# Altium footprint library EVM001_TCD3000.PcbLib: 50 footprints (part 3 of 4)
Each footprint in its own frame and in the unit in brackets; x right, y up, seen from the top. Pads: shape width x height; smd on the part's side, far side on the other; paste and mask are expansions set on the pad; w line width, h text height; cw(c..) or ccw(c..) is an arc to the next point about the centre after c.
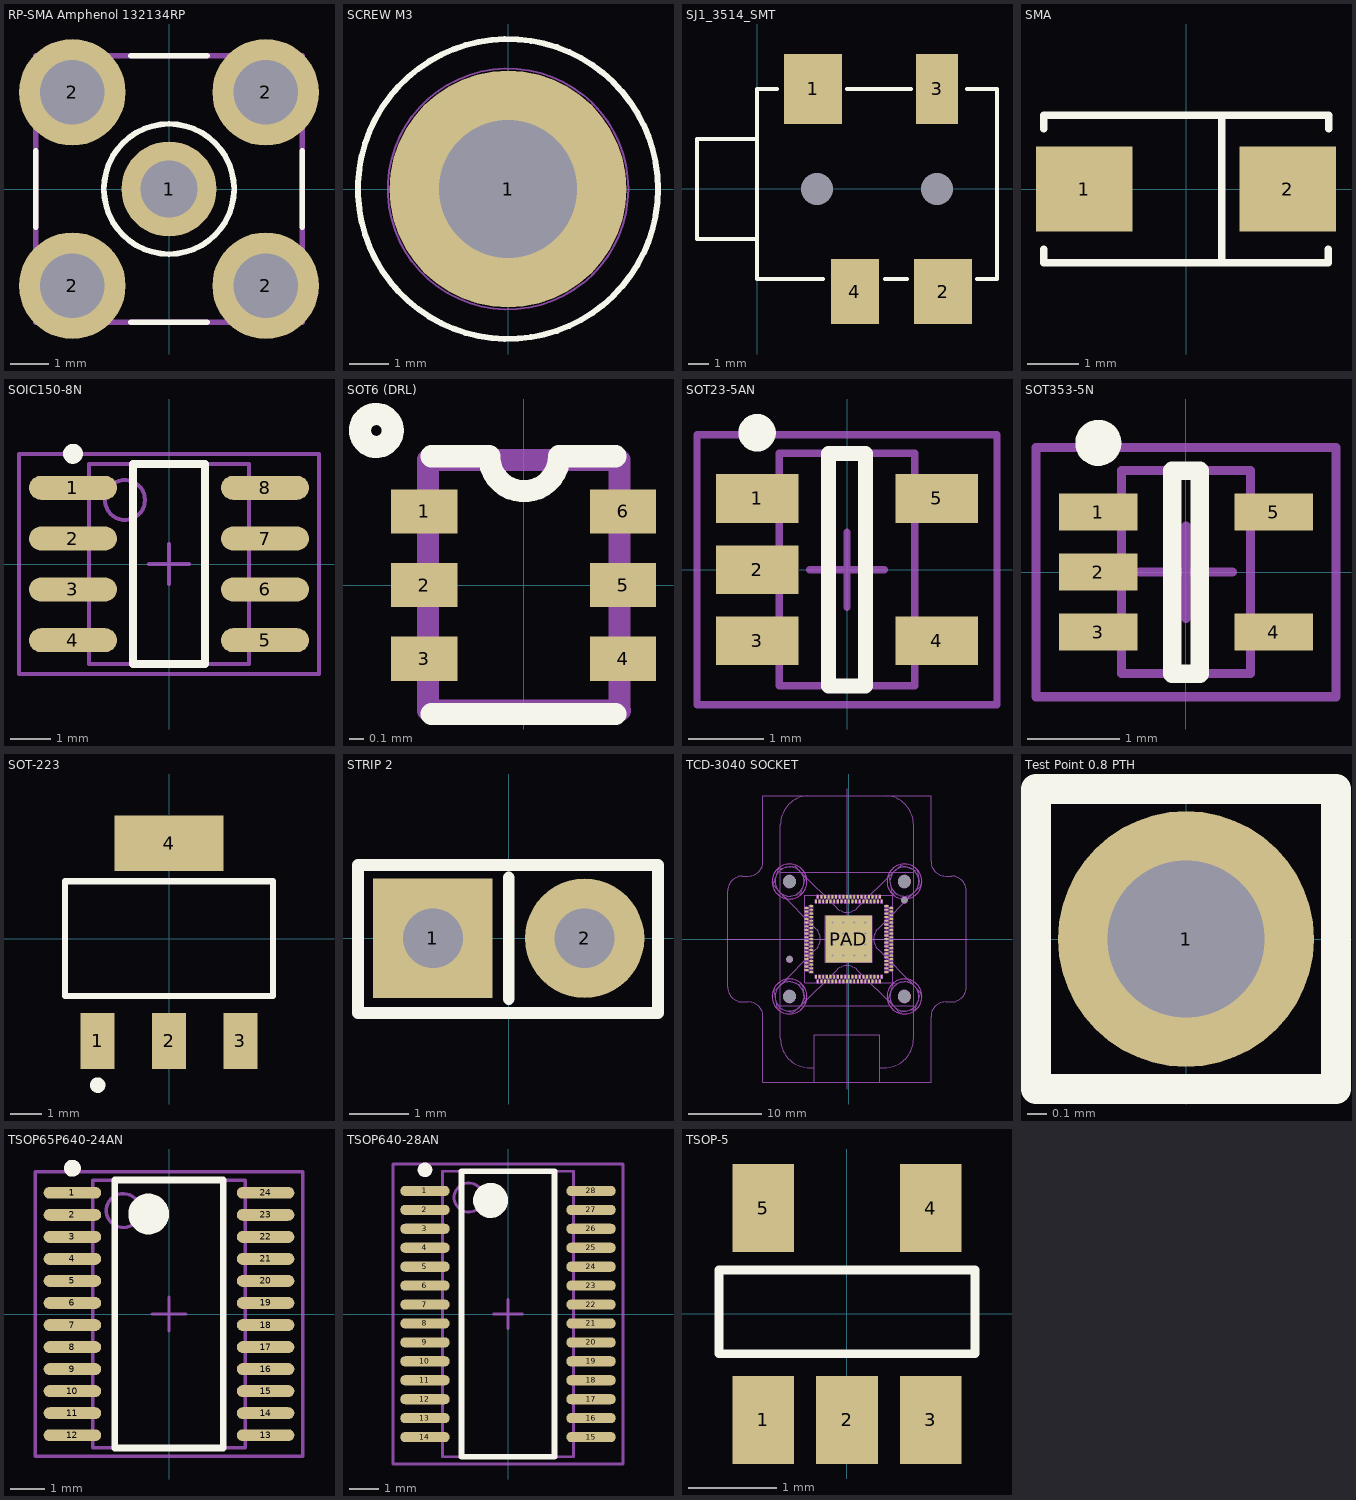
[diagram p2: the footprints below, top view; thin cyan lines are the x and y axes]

## RP-SMA Amphenol 132134RP [mm]
pads (5):
  round 2.5 hole 1.5: 1(0,0)
  round 2.8 hole 1.7: 2(-2.54,-2.54) 2(-2.54,2.54) 2(2.54,-2.54) 2(2.54,2.54)
Top Overlay:
  circle w0.15: c0,0 r1.71
  lines w0.15: -3.5,-1 -3.5,1 ; -1,-3.5 1,-3.5 ; -1,3.5 1,3.5 ; 3.5,-1 3.5,1
Mechanical 10:
  lines w0.156: -3.5,-3.5 -3.5,3.5 3.5,3.5 3.5,-3.5 -3.5,-3.5
3D body: height 9.6, standoff -3.87, extent -3.175,-3.175 3.175,3.175

## SCREW M3 [mm] "Vite 3mm"
pads (1):
  round 6 hole 3.5: 1(0,0)
Top Overlay:
  circle w0.15: c0,0 r3.8
Mechanical 10:
  circle w0.051: c0,0 r3.048
3D body: height 4, standoff 0, extent -3.057,-3.057 3.057,3.057

## SJ1_3514_SMT [mm]
pads (6):
  round 0 hole 1.6: 0(3,0) 0(9,0)
  rect 2.9x3.5 smd: 1(2.8,5)
  rect 2.9x3.25 smd: 2(9.3,-5.125)
  rect 2.1x3.5 smd: 3(9,5)
  rect 2.4x3.25 smd: 4(4.9,-5.125)
Top Overlay:
  lines w0.203: 0,-2.5 -3,-2.5 -3,2.5 0,2.5 ; 1,5 0,5 0,-4.5 3.3,-4.5 ; 4.5,5 7.7,5 ; 6.4,-4.5 7.5,-4.5 ; 10.5,5 12,5 12,-4.5 11,-4.5
3D body: height 5, standoff -2, extent -2.678,-4.912 11.822,5.588

## SMA [mm] "SMA Diodes Case"
pads (2):
  rect 1.9x1.68 smd: 1(-2,0) 2(2,0)
Top Overlay:
  lines w0.15: -2.8,-1.19 -2.8,-1.45 2.8,-1.45 2.8,-1.19 ; -2.8,1.19 -2.8,1.45 2.8,1.45 ; 0.7,-1.45 0.7,1.45 ; 2.81,1.19 2.81,1.45
3D body: height 2.4, standoff 0, extent -2.6,-1.3 2.6,1.3

## SOIC150-8N [mm]
pads (8):
  oval 2.2x0.6 smd: 1(-2.4,1.905) 2(-2.4,0.635) 3(-2.4,-0.635) 4(-2.4,-1.905) 5(2.4,-1.905) 6(2.4,-0.635) 7(2.4,0.635) 8(2.4,1.905)
Top Overlay:
  circle w0.25: c-2.4,2.755 r0.125
  lines w0.2: -0.9,-2.5 -0.9,2.5 0.9,2.5 0.9,-2.5 -0.9,-2.5
Mechanical 13:
  circle w0.1: c-1.1,1.6 r0.5
  lines w0.1: -2,-2.5 -2,2.5 2,2.5 2,-2.5 -2,-2.5
Mechanical 15:
  lines w0.1: -0.5,0 0.5,0 ; 0,-0.5 0,0.5 ; -3.75,-2.75 -3.75,2.75 3.75,2.75 3.75,-2.75 -3.75,-2.75
3D body: height 1.75, standoff 0, extent -2.917,-2.388 2.883,2.412

## SOT6 (DRL) [mm]
pads (6):
  rect 0.45x0.3 smd: 1(-0.675,0.5) 2(-0.675,0) 3(-0.675,-0.5) 4(0.675,-0.5) 5(0.675,0) 6(0.675,0.5)
Top Overlay:
  circle w0.15: c-1,1.05 r0.112
  lines w0.15: -0.625,-0.875 0.623,-0.875 ; -0.625,0.875 -0.235,0.875 ; -0.234,0.875 ccw(c0.004,0.875) 0.241,0.875 0.623,0.875
Mechanical 10:
  lines w0.15: -0.65,-0.85 -0.65,0.85 0.65,0.85 0.65,-0.85 ; -0.646,-0.85 0.654,-0.85
3D body: height 0.6, standoff 0, extent -0.65,-0.85 0.654,0.85

## SOT23-5AN [mm] "SOT23, 5-Leads, Body 2.9x1.6mm, Pitch 0.95mm, Lead Span 2.8mm, IPC Medium Density"
height 1.45
pads (5):
  rect 1.1x0.65 smd: 1(-1.2,0.95) 2(-1.2,0) 3(-1.2,-0.95) 4(1.2,-0.95) 5(1.2,0.95)
Top Overlay:
  circle w0.25: c-1.2,1.825 r0.125
  lines w0.2: -0.25,-1.55 0.25,-1.55 0.25,1.55 -0.25,1.55 -0.25,-1.55
Mechanical 13:
  lines w0.1: -0.9,-1.55 -0.9,1.55 0.9,1.55 0.9,-1.55 -0.9,-1.55
Mechanical 15:
  lines w0.1: -0.5,0 0.5,0 ; 0,-0.5 0,0.5 ; -2,-1.8 -2,1.8 2,1.8 2,-1.8 -2,-1.8
3D body: height 1.45, standoff 0, extent -0.9,-1.55 0.9,1.55

## SOT353-5N [mm] "SOT353, 5-Leads, Body 2x1.3mm, Pitch 0.65mm, Lead Span 2.1mm, IPC Medium Density"
height 1.1
pads (5):
  rect 0.85x0.4 smd: 1(-0.95,0.65) 2(-0.95,0) 3(-0.95,-0.65) 4(0.95,-0.65) 5(0.95,0.65)
Top Overlay:
  circle w0.25: c-0.95,1.4 r0.125
  lines w0.2: -0.15,-1.1 -0.15,1.1 0.15,1.1 0.15,-1.1 -0.15,-1.1
Mechanical 13:
  lines w0.1: -0.7,-1.1 0.7,-1.1 0.7,1.1 -0.7,1.1 -0.7,-1.1
Mechanical 15:
  lines w0.1: -0.5,0 0.5,0 ; 0,-0.5 0,0.5 ; -1.625,-1.35 1.625,-1.35 1.625,1.35 -1.625,1.35 -1.625,-1.35
3D body: height 1.1, standoff 0, extent -0.7,-1.1 0.7,1.1

## SOT-223 [mm]
height 1.6
pads (4):
  rect 1.1x1.8 smd: 1(-2.3,-3.3) 2(0,-3.3) 3(2.3,-3.3)
  rect 3.5x1.8 smd: 4(0,3.074)
Top Overlay:
  circle w0.25: c-2.3,-4.725 r0.125
  lines w0.2: -3.35,-1.85 3.35,-1.85 3.35,1.85 -3.35,1.85 -3.35,-1.85
3D body: height 1.8, standoff 0.1, extent -3.25,-3.45 3.25,3.441

## STRIP 2 [mm]
pads (2):
  rect 2x2 hole 1: 1(-1.27,0)
  round 2 hole 1: 2(1.27,0)
Top Overlay:
  lines w0.2: 0,-1.016 0,1.016 ; -2.525,-1.25 2.5,-1.25 2.5,1.225 -2.525,1.225 -2.525,-1.25
3D body: height 8.51, standoff -2.99, extent -2.54,-1.27 2.54,1.27

## TCD3000 [mm] "QFN_40_88PIN"

## TCD-3040 SOCKET [mm]
pads (171):
  rect 0.5x0.25 smd: A1(-5.8,4.25) A2(-5.8,3.75) A3(-5.8,3.25) A4(-5.8,2.75) A5(-5.8,2.25) A6(-5.8,1.75) A7(-5.8,1.25) A8(-5.8,0.75) A9(-5.8,0.25) A10(-5.8,-0.25) A11(-5.8,-0.75) A12(-5.8,-1.25) A13(-5.8,-1.75) A14(-5.8,-2.25) A15(-5.8,-2.75) A16(-5.8,-3.25) A17(-5.8,-3.75) A18(-5.8,-4.25) A37(5.8,-4.25) A38(5.8,-3.75) A39(5.8,-3.25) A40(5.8,-2.75) A41(5.8,-2.25) A42(5.8,-1.75) A43(5.8,-1.25) A44(5.8,-0.75) A45(5.8,-0.25) A46(5.8,0.25) A47(5.8,0.75) A48(5.8,1.25) A49(5.8,1.75) A50(5.8,2.25) A51(5.8,2.75) A52(5.8,3.25) A53(5.8,3.75) A54(5.8,4.25) B1(-5.15,4.5) B2(-5.15,4) B3(-5.15,3.5) B4(-5.15,3) B5(-5.15,2.5) B6(-5.15,2) B7(-5.15,1.5) B8(-5.15,1) B9(-5.15,0.5) B10(-5.15,0) B11(-5.15,-0.5) B12(-5.15,-1) B13(-5.15,-1.5) B14(-5.15,-2) B15(-5.15,-2.5) B16(-5.15,-3) B17(-5.15,-3.5) B18(-5.15,-4) B19(-5.15,-4.5) B39(5.15,-4.5) B40(5.15,-4) B41(5.15,-3.5) B42(5.15,-3) B43(5.15,-2.5) B44(5.15,-2) B45(5.15,-1.5) B46(5.15,-1) B47(5.15,-0.5) B48(5.15,0) B49(5.15,0.5) B50(5.15,1) B51(5.15,1.5) B52(5.15,2) B53(5.15,2.5) B54(5.15,3) B55(5.15,3.5) B56(5.15,4) B57(5.15,4.5)
  rect 0.25x0.5 smd: A19(-4.25,-5.8) A20(-3.75,-5.8) A21(-3.25,-5.8) A22(-2.75,-5.8) A23(-2.25,-5.8) A24(-1.75,-5.8) A25(-1.25,-5.8) A26(-0.75,-5.8) A27(-0.25,-5.8) A28(0.25,-5.8) A29(0.75,-5.8) A30(1.25,-5.8) A31(1.75,-5.8) A32(2.25,-5.8) A33(2.75,-5.8) A34(3.25,-5.8) A35(3.75,-5.8) A36(4.25,-5.8) A55(4.25,5.8) A56(3.75,5.8) A57(3.25,5.8) A58(2.75,5.8) A59(2.25,5.8) A60(1.75,5.8) A61(1.25,5.8) A62(0.75,5.8) A63(0.25,5.8) A64(-0.25,5.8) A65(-0.75,5.8) A66(-1.25,5.8) A67(-1.75,5.8) A68(-2.25,5.8) A69(-2.75,5.8) A70(-3.25,5.8) A71(-3.75,5.8) A72(-4.25,5.8) B20(-4.5,-5.15) B21(-4,-5.15) B22(-3.5,-5.15) B23(-3,-5.15) B24(-2.5,-5.15) B25(-2,-5.15) B26(-1.5,-5.15) B27(-1,-5.15) B28(-0.5,-5.15) B29(0,-5.15) B30(0.5,-5.15) B31(1,-5.15) B32(1.5,-5.15) B33(2,-5.15) B34(2.5,-5.15) B35(3,-5.15) B36(3.5,-5.15) B37(4,-5.15) B38(4.5,-5.15) B58(4.5,5.15) B59(4,5.15) B60(3.5,5.15) B61(3,5.15) B62(2.5,5.15) B63(2,5.15) B64(1.5,5.15) B65(1,5.15) B66(0.5,5.15) B67(0,5.15) B68(-0.5,5.15) B69(-1,5.15) B70(-1.5,5.15) B71(-2,5.15) B72(-2.5,5.15) B73(-3,5.15) B74(-3.5,5.15) B75(-4,5.15) B76(-4.5,5.15)
  round 0.3 hole 0.3 mask+0: PAD(-2.25,-2.25) PAD(-2.25,-0.75) PAD(-2.25,0.75) PAD(-2.25,2.25) PAD(-0.75,-2.25) PAD(-0.75,-0.75) PAD(-0.75,0.75) PAD(-0.75,2.25) PAD(0.75,-2.25) PAD(0.75,-0.75) PAD(0.75,0.75) PAD(0.75,2.25) PAD(2.25,-2.25) PAD(2.25,-0.75) PAD(2.25,0.75) PAD(2.25,2.25)
  rect 6.4x6.4 smd: PAD(0,0)
  round 0.85 hole 0.85 unplated mask+0: ""(-8.113,-2.782) ""(7.613,5.323)
  round 1.71 hole 1.7 unplated mask+0: ""(-8.113,-7.863) ""(-8.113,7.863) ""(7.613,-7.863) ""(7.613,7.863)
Keep-Out Layer:
  circle w0.1: c-8.113,7.863 r2.4
  circle w0.1: c-8.113,-7.863 r2.4
  circle w0.1: c7.613,-7.863 r2.4
  circle w0.1: c7.613,7.863 r2.4
Mechanical 2:
  drawing of 864 lines, arcs and shapes, not listed
Mechanical 3:
  drawing of 686 lines, arcs and shapes, not listed
Mechanical 10:
  lines w0.05: -6,-6 -6,6 6,6 6,-6 -6,-6
3D body: height 0.9, standoff 0, extent -6,-6 6,6

## Test Point 0.8 PTH [mm] "Test Point 0.8mm PTH"
pads (1):
  round 1.3 hole 0.8: 1(0,0)
Top Overlay:
  lines w0.15: -0.762,-0.762 0.762,-0.762 0.762,0.762 -0.762,0.762 -0.762,-0.762
Mechanical 10:
  lines w0.051: -0.762,-0.762 -0.762,0.762 0.762,0.762 0.762,-0.762 -0.762,-0.762
3D body: height 1, standoff 0, extent -0.762,-0.762 0.762,0.762

## TSOP65P640-24AN [mm] "TSOP, 24-Leads, Body 7.8x4.4mm, Pitch 0.65mm, IPC Medium Density"
height 1.1
pads (24):
  oval 1.7x0.35 smd: 1(-2.85,3.575) 2(-2.85,2.925) 3(-2.85,2.275) 4(-2.85,1.625) 5(-2.85,0.975) 6(-2.85,0.325) 7(-2.85,-0.325) 8(-2.85,-0.975) 9(-2.85,-1.625) 10(-2.85,-2.275) 11(-2.85,-2.925) 12(-2.85,-3.575) 13(2.85,-3.575) 14(2.85,-2.925) 15(2.85,-2.275) 16(2.85,-1.625) 17(2.85,-0.975) 18(2.85,-0.325) 19(2.85,0.325) 20(2.85,0.975) 21(2.85,1.625) 22(2.85,2.275) 23(2.85,2.925) 24(2.85,3.575)
Top Overlay:
  circle w0.25: c-2.85,4.3 r0.125
  circle w0.6: c-0.6,2.95 r0.3
  lines w0.2: -1.6,-3.95 -1.6,3.95 1.6,3.95 1.6,-3.95 -1.6,-3.95
Mechanical 13:
  circle w0.1: c-1.35,3.05 r0.5
  lines w0.1: -2.25,-3.95 -2.25,3.95 2.25,3.95 2.25,-3.95 -2.25,-3.95
Mechanical 15:
  lines w0.1: -0.5,0 0.5,0 ; 0,-0.5 0,0.5 ; -3.95,-4.2 -3.95,4.2 3.95,4.2 3.95,-4.2 -3.95,-4.2
3D body: height 1.1, standoff 0, extent -2.25,-3.95 2.25,3.95

## TSOP640-28AN [mm] "TSOP, 28-Leads, Body 9.7x4.4mm, Pitch 0.65mm, IPC Medium Density"
height 1.1
pads (28):
  oval 1.7x0.35 smd: 1(-2.85,4.225) 2(-2.85,3.575) 3(-2.85,2.925) 4(-2.85,2.275) 5(-2.85,1.625) 6(-2.85,0.975) 7(-2.85,0.325) 8(-2.85,-0.325) 9(-2.85,-0.975) 10(-2.85,-1.625) 11(-2.85,-2.275) 12(-2.85,-2.925) 13(-2.85,-3.575) 14(-2.85,-4.225) 15(2.85,-4.225) 16(2.85,-3.575) 17(2.85,-2.925) 18(2.85,-2.275) 19(2.85,-1.625) 20(2.85,-0.975) 21(2.85,-0.325) 22(2.85,0.325) 23(2.85,0.975) 24(2.85,1.625) 25(2.85,2.275) 26(2.85,2.925) 27(2.85,3.575) 28(2.85,4.225)
Top Overlay:
  circle w0.6: c-0.6,3.9 r0.3
  circle w0.25: c-2.85,4.95 r0.125
  lines w0.2: -1.6,-4.9 1.6,-4.9 1.6,4.9 -1.6,4.9 -1.6,-4.9
Mechanical 13:
  circle w0.1: c-1.35,4 r0.5
  lines w0.1: -2.25,-4.9 2.25,-4.9 2.25,4.9 -2.25,4.9 -2.25,-4.9
Mechanical 15:
  lines w0.1: -0.5,0 0.5,0 ; 0,-0.5 0,0.5 ; -3.95,-5.15 3.95,-5.15 3.95,5.15 -3.95,5.15 -3.95,-5.15
3D body: height 1.1, standoff 0, extent -2.25,-4.9 2.25,4.9

## TSOP-5 [mm]
height 1.45
pads (5):
  rect 0.7x1 smd: 1(-0.95,-1.2) 2(0,-1.2) 3(0.95,-1.2) 4(0.95,1.2) 5(-0.95,1.2)
Top Overlay:
  lines w0.1: -1.45,-0.45 -1.45,0.5 1.45,0.5 1.45,-0.45 -1.45,-0.45
3D body: height 1.1, standoff 0, extent -1.5,-1.25 1.5,1.25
